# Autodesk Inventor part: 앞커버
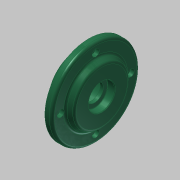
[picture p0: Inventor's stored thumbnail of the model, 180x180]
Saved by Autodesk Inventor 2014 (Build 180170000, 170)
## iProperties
Created: 2015-11
Part Number: 앞커버
Material: 일반
Document SubType Name: Modeling
Designer: mduedu
Density: 1 g/cm^3
Appearance: 매끄러움 - 짙은 바다 녹색
Mass: 107.02 g
Surface Area: 234.647 cm^2
Volume: 107.02 cm^3
Author: mduedu
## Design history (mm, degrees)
sketch "스케치1"
  geometry: C1 r 50 at (0, 0); 1 further point
  constraints: 1 centre point, 1 coincident
  dimensions: "d57" = 100 diameter of C1
extrude "돌출1" new body sketch "스케치1" distance "d3" = 8; taper "d4" = 0 deg
sketch "스케치2"
  geometry: C1 r 35 at (0, 0); 1 further point
  constraints: 1 centre point, 1 coincident
  dimensions: "d5" = 70 diameter of C1
extrude "돌출2" join sketch "스케치2" distance "d6" = 7; taper "d7" = -30 deg
sketch "스케치3" dims "d58" = 80
  geometry: 3 further points
  constraints: 2 vertical alignment, 1 coincident, 2 other
hole "구멍1" sketch "스케치3" at (0, 40) diameter "d11" = 4.5; stored, may be unused: countersink angle "d15" = 90 deg, drill point angle "d17" = 118 deg; dims "d12" = 6, "d13" = 8, "d14" = 4.4, "d16" = 8
sketch "스케치4"
  geometry: C1 r 35 at (0, 0); 1 further point
  constraints: 1 centre point, 1 coincident
  dimensions: "d21" = 70 diameter of C1
extrude "돌출3" join sketch "스케치4" distance "d23" = 12; taper "d24" = 0 deg
hole "구멍2" diameter "d27" = 30; stored, may be unused: countersink angle "d31" = 90 deg, drill point angle "d33" = 0 deg; dims "d25" = 10, "d26" = 10, "d28" = 6, "d29" = 40, "d30" = 12, "d32" = 15
fillet "모깎기3" dims "d36" = 3
fillet "모깎기4" dims "d37" = 3
fillet "모깎기5" dims "d38" = 0.3
chamfer "모따기1" distance "d39" = 1; stored, may be unused: second distance "d40" = 2, angle "d41" = 45 deg
hole "구멍3" diameter "d44" = 20; stored, may be unused: countersink angle "d48" = 90 deg, drill point angle "d50" = 118 deg; dims "d45" = 6, "d46" = 30, "d47" = 8.3, "d49" = 8, "d59" = 10, "d60" = 10
fillet "모깎기6" dims "d51" = 0.3
chamfer "모따기2" distance "d52" = 0.8; stored, may be unused: second distance "d53" = 2, angle "d54" = 30 deg
node "솔리드1"
pattern_circular "원형 패턴1" dims angle "d19" = 360 deg
